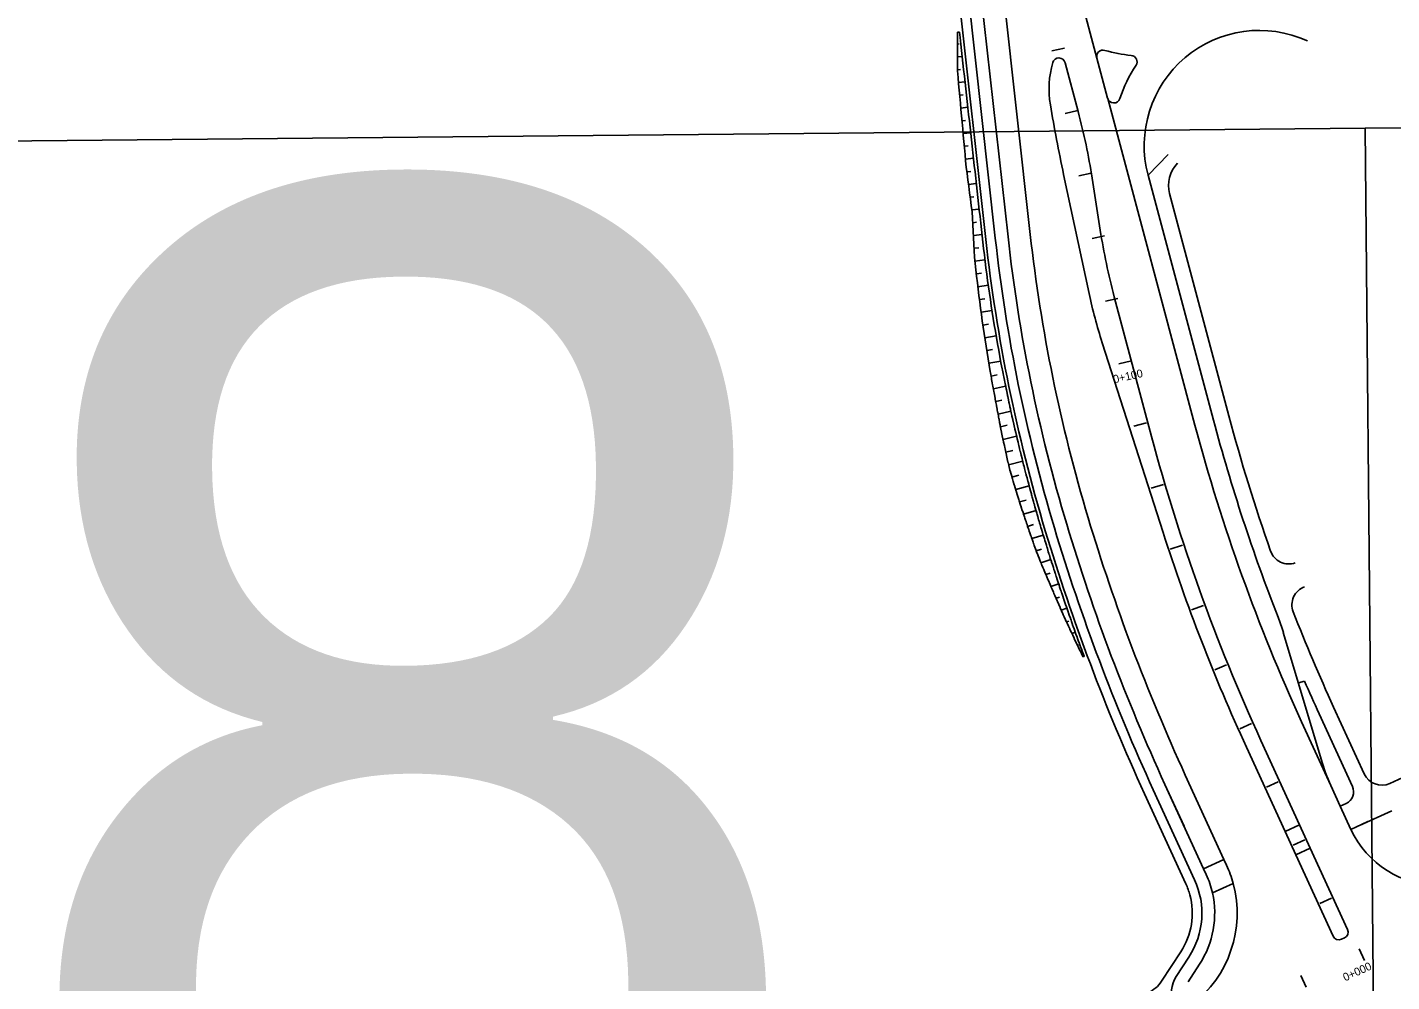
# Model space of a CAD drawing. Extents: x 6503541 to 6503743, y 5888004 to 5888145.
# Drawn here: x 6503621.98 to 6503627.1, y 5888065.98 to 5888069.56 of the extents above; entities that cross this region are included whole.
import ezdxf

# ---------------------------------------------------------------- set-up
doc = ezdxf.new("R2010")
doc.units = 0
doc.layers.add('12', color=7, linetype='Continuous')
doc.layers.add('tabela', color=7, linetype='Continuous')

msp = doc.modelspace()

# ---------------------------------------------------------------- linework, layer by layer
at = {"layer": '12'}
for p, q in [((6503625.4273, 5888070.0972), (6503625.5753, 5888068.7684)), ((6503625.4631, 5888070.1011), (6503625.6111, 5888068.7724)), ((6503625.5108, 5888070.1065), (6503625.6588, 5888068.7777)), ((6503625.5943, 5888070.1158), (6503625.7422, 5888068.787)), ((6503625.9923, 5888069.4479), (6503625.8125, 5888070.1213)), ((6503625.9216, 5888069.2472), (6503625.8727, 5888069.4307)), ((6503626.0324, 5888069.2976), (6503625.9923, 5888069.4479)), ((6503626.3595, 5888068.0721), (6503626.0325, 5888069.297)), ((6503625.8673, 5888069.012), (6503625.9627, 5888068.5658)), ((6503625.9742, 5888068.9979), (6503626.0046, 5888068.8027)), ((6503626.429, 5888068.0907), (6503626.1841, 5888069.0085)), ((6503626.487, 5888068.1062), (6503626.2645, 5888068.9399)), ((6503626.1972, 5888068.0288), (6503626.0571, 5888068.5534)), ((6503626.012, 5888068.3807), (6503626.2401, 5888067.6695)), ((6503626.487, 5888068.1062), (6503626.4909, 5888068.0915)), ((6503626.6911, 5888067.2944), (6503626.8337, 5888066.8153)), ((6503626.7474, 5888067.1053), (6503626.7704, 5888067.1121)), ((6503626.9948, 5888066.7636), (6503626.8797, 5888067.0145)), ((6503626.8693, 5888066.7205), (6503626.7598, 5888066.9595)), ((6503626.9503, 5888066.7168), (6503626.8252, 5888066.9895)), ((6503626.6976, 5888066.5481), (6503626.5525, 5888066.8645)), ((6503626.7521, 5888066.5731), (6503626.607, 5888066.8895)), ((6503626.4685, 5888066.4431), (6503626.3234, 5888066.7595)), ((6503627.0903, 5888066.7282), (6503627.156, 5888066.7583)), ((6503626.3585, 5888066.3663), (6503626.2034, 5888066.7044)), ((6503626.3192, 5888066.5672), (6503626.2471, 5888066.7244)), ((6503626.3921, 5888066.4081), (6503626.2471, 5888066.7244)), ((6503626.9048, 5888066.6431), (6503626.8693, 5888066.7205)), ((6503626.3258, 5888066.3512), (6503626.1707, 5888066.6894)), ((6503626.9266, 5888066.6531), (6503626.9048, 5888066.6431)), ((6503626.9448, 5888066.5559), (6503626.9048, 5888066.6431)), ((6503627.0975, 5888066.6259), (6503626.9767, 5888066.5705)), ((6503626.6976, 5888066.5481), (6503626.7521, 5888066.5731)), ((6503626.7376, 5888066.4608), (6503626.6976, 5888066.5481)), ((6503626.7921, 5888066.4858), (6503626.7521, 5888066.5731)), ((6503627.0079, 5888066.5848), (6503626.9448, 5888066.5559)), ((6503626.3921, 5888066.4081), (6503626.4685, 5888066.4431)), ((6503626.4785, 5888066.4213), (6503626.4685, 5888066.4431)), ((6503626.7376, 5888066.4608), (6503626.7921, 5888066.4858)), ((6503626.8776, 5888066.1554), (6503626.7376, 5888066.4608)), ((6503626.9321, 5888066.1804), (6503626.7921, 5888066.4858)), ((6503626.4021, 5888066.3863), (6503626.3921, 5888066.4081)), ((6503626.4253, 5888066.3177), (6503626.503, 5888066.3533)), ((6503626.9203, 5888066.1486), (6503626.9094, 5888066.1436)), ((6503626.3068, 5888066.0968), (6503626.2348, 5888065.9866)), ((6503626.3369, 5888066.0771), (6503626.2896, 5888066.0046)), ((6503626.3771, 5888066.0508), (6503626.3338, 5888065.9845))]:
    msp.add_line(p, q, dxfattribs=at)
for points in [[(6503625.4688, 5888069.5449), (6503625.4766, 5888069.5458)], [(6503625.9396, 5888067.2029), (6503625.9391, 5888067.2039), (6503625.9337, 5888067.2152), (6503625.9291, 5888067.2248), (6503625.9283, 5888067.2266), (6503625.9228, 5888067.238), (6503625.9181, 5888067.248), (6503625.9175, 5888067.2494), (6503625.9121, 5888067.2608), (6503625.9072, 5888067.2712), (6503625.9067, 5888067.2722), (6503625.9014, 5888067.2836), (6503625.8963, 5888067.2945), (6503625.896, 5888067.2951), (6503625.8907, 5888067.3065), (6503625.8901, 5888067.3079), (6503625.8855, 5888067.3178), (6503625.8854, 5888067.318), (6503625.8802, 5888067.3294), (6503625.878, 5888067.3342), (6503625.8749, 5888067.3409), (6503625.8748, 5888067.3412), (6503625.8697, 5888067.3524), (6503625.8661, 5888067.3605), (6503625.8645, 5888067.3639), (6503625.8642, 5888067.3646), (6503625.8594, 5888067.3754), (6503625.8542, 5888067.3869), (6503625.8542, 5888067.387), (6503625.8537, 5888067.3881), (6503625.8491, 5888067.3985), (6503625.844, 5888067.4101), (6503625.8433, 5888067.4116), (6503625.8425, 5888067.4134), (6503625.8389, 5888067.4216), (6503625.8339, 5888067.4332), (6503625.833, 5888067.4352), (6503625.831, 5888067.4399), (6503625.8288, 5888067.4448), (6503625.8238, 5888067.4564), (6503625.8228, 5888067.4588), (6503625.8195, 5888067.4665), (6503625.8189, 5888067.468), (6503625.8139, 5888067.4797), (6503625.8127, 5888067.4825), (6503625.809, 5888067.4913), (6503625.8082, 5888067.4932), (6503625.8041, 5888067.5029), (6503625.8027, 5888067.5062), (6503625.7992, 5888067.5146), (6503625.797, 5888067.5199), (6503625.7943, 5888067.5263), (6503625.7928, 5888067.53), (6503625.7895, 5888067.5379), (6503625.7859, 5888067.5466), (6503625.7847, 5888067.5496), (6503625.783, 5888067.5538), (6503625.7799, 5888067.5613), (6503625.7751, 5888067.5731), (6503625.775, 5888067.5735), (6503625.7733, 5888067.5776), (6503625.7704, 5888067.5848), (6503625.7658, 5888067.5966), (6503625.7644, 5888067.6004), (6503625.764, 5888067.6016), (6503625.7615, 5888067.6084), (6503625.7573, 5888067.6203), (6503625.7553, 5888067.6258), (6503625.7547, 5888067.6277), (6503625.753, 5888067.6322), (6503625.7488, 5888067.6441), (6503625.7468, 5888067.6501), (6503625.7451, 5888067.655), (6503625.7447, 5888067.656), (6503625.7405, 5888067.668), (6503625.7383, 5888067.6744), (6503625.7364, 5888067.6799), (6503625.7356, 5888067.6823), (6503625.7323, 5888067.6919), (6503625.73, 5888067.6987), (6503625.7283, 5888067.7038), (6503625.7263, 5888067.7097), (6503625.7243, 5888067.7158), (6503625.7218, 5888067.7231), (6503625.7203, 5888067.7278), (6503625.7172, 5888067.7372), (6503625.7163, 5888067.7398), (6503625.7138, 5888067.7475), (6503625.7124, 5888067.7518), (6503625.7085, 5888067.7638), (6503625.7082, 5888067.7647), (6503625.7059, 5888067.772), (6503625.7046, 5888067.7758), (6503625.7008, 5888067.7878), (6503625.6994, 5888067.7922), (6503625.6981, 5888067.7965), (6503625.697, 5888067.7999), (6503625.6932, 5888067.8119), (6503625.6908, 5888067.8198), (6503625.6904, 5888067.8211), (6503625.6895, 5888067.824), (6503625.6858, 5888067.8361), (6503625.6828, 5888067.8457), (6503625.6823, 5888067.8475), (6503625.6821, 5888067.8481), (6503625.6784, 5888067.8602), (6503625.6754, 5888067.8703), (6503625.6748, 5888067.8723), (6503625.674, 5888067.8752), (6503625.6712, 5888067.8844), (6503625.6681, 5888067.895), (6503625.6677, 5888067.8966), (6503625.6658, 5888067.903), (6503625.6642, 5888067.9087), (6503625.6616, 5888067.9198), (6503625.6614, 5888067.921), (6503625.6591, 5888067.9311), (6503625.6586, 5888067.9333), (6503625.6559, 5888067.9449), (6503625.6558, 5888067.9457), (6503625.653, 5888067.958), (6503625.6527, 5888067.9594), (6503625.6504, 5888067.9701), (6503625.6503, 5888067.9703), (6503625.6477, 5888067.9827), (6503625.6466, 5888067.9877), (6503625.645, 5888067.995), (6503625.645, 5888067.9952), (6503625.6424, 5888068.0074), (6503625.6406, 5888068.016), (6503625.6398, 5888068.0198), (6503625.6397, 5888068.0204), (6503625.6373, 5888068.0321), (6503625.6348, 5888068.0443), (6503625.6347, 5888068.0445), (6503625.6345, 5888068.0456), (6503625.6322, 5888068.0569), (6503625.6298, 5888068.0693), (6503625.6295, 5888068.0708), (6503625.6291, 5888068.0727), (6503625.6274, 5888068.0817), (6503625.625, 5888068.0941), (6503625.6246, 5888068.0961), (6503625.6236, 5888068.1011), (6503625.6226, 5888068.1065), (6503625.6203, 5888068.1189), (6503625.6198, 5888068.1213), (6503625.6183, 5888068.1295), (6503625.6179, 5888068.1313), (6503625.6157, 5888068.1437), (6503625.6151, 5888068.1466), (6503625.6134, 5888068.1561), (6503625.6111, 5888068.1685), (6503625.6104, 5888068.1719), (6503625.6087, 5888068.1809), (6503625.6064, 5888068.1933), (6503625.6057, 5888068.1972), (6503625.6041, 5888068.2058), (6503625.6019, 5888068.2182), (6503625.6011, 5888068.2224), (6503625.5996, 5888068.2306), (6503625.5974, 5888068.243), (6503625.5966, 5888068.2477), (6503625.5952, 5888068.2554), (6503625.5931, 5888068.2679), (6503625.5923, 5888068.2727), (6503625.5882, 5888068.2964), (6503625.5843, 5888068.3201), (6503625.5804, 5888068.3438), (6503625.5766, 5888068.3676), (6503625.573, 5888068.3913), (6503625.5694, 5888068.4151), (6503625.5658, 5888068.4389), (6503625.5624, 5888068.4627), (6503625.5591, 5888068.4865), (6503625.5558, 5888068.5104), (6503625.5527, 5888068.5342), (6503625.5496, 5888068.5581), (6503625.5467, 5888068.582), (6503625.5438, 5888068.6059), (6503625.541, 5888068.6299), (6503625.5383, 5888068.6539), (6503625.5356, 5888068.6778), (6503625.5334, 5888068.7019), (6503625.5319, 5888068.7261), (6503625.5306, 5888068.7504), (6503625.5293, 5888068.7746), (6503625.528, 5888068.7989), (6503625.5267, 5888068.8232), (6503625.5254, 5888068.8474), (6503625.5237, 5888068.8716), (6503625.5207, 5888068.8955), (6503625.5176, 5888068.9194), (6503625.5146, 5888068.9433), (6503625.5115, 5888068.9672), (6503625.5085, 5888068.9911), (6503625.5055, 5888069.015), (6503625.5024, 5888069.0389), (6503625.4997, 5888069.0628), (6503625.4975, 5888069.0869), (6503625.4953, 5888069.111), (6503625.4932, 5888069.1351), (6503625.491, 5888069.1591), (6503625.4888, 5888069.1832), (6503625.4866, 5888069.2073), (6503625.4844, 5888069.2314), (6503625.4823, 5888069.2554), (6503625.4801, 5888069.2795), (6503625.4779, 5888069.3036), (6503625.4757, 5888069.3277), (6503625.4735, 5888069.3517), (6503625.4714, 5888069.3758), (6503625.4693, 5888069.3999), (6503625.4694, 5888069.4245), (6503625.4695, 5888069.4491), (6503625.4696, 5888069.4736), (6503625.4697, 5888069.4982), (6503625.4699, 5888069.5228), (6503625.4688, 5888069.5449)], [(6503625.9441, 5888067.2045), (6503625.9437, 5888067.2056), (6503625.9394, 5888067.2173), (6503625.9357, 5888067.2272), (6503625.935, 5888067.2291), (6503625.9307, 5888067.2409), (6503625.9269, 5888067.2512), (6503625.9264, 5888067.2526), (6503625.9221, 5888067.2644), (6503625.9182, 5888067.2752), (6503625.9178, 5888067.2762), (6503625.9136, 5888067.288), (6503625.9096, 5888067.2992), (6503625.9093, 5888067.2998), (6503625.9051, 5888067.3116), (6503625.9046, 5888067.3131), (6503625.901, 5888067.3233), (6503625.9009, 5888067.3235), (6503625.8968, 5888067.3353), (6503625.8951, 5888067.3402), (6503625.8926, 5888067.3471), (6503625.8925, 5888067.3474), (6503625.8885, 5888067.359), (6503625.8856, 5888067.3673), (6503625.8844, 5888067.3708), (6503625.8841, 5888067.3715), (6503625.8803, 5888067.3827), (6503625.8762, 5888067.3945), (6503625.8762, 5888067.3945), (6503625.8758, 5888067.3957), (6503625.8722, 5888067.4064), (6503625.8681, 5888067.4183), (6503625.8676, 5888067.4198), (6503625.867, 5888067.4217), (6503625.8641, 5888067.4301), (6503625.8601, 5888067.442), (6503625.8594, 5888067.444), (6503625.8578, 5888067.4489), (6503625.8561, 5888067.4539), (6503625.8522, 5888067.4658), (6503625.8514, 5888067.4683), (6503625.8488, 5888067.4762), (6503625.8482, 5888067.4777), (6503625.8443, 5888067.4896), (6503625.8434, 5888067.4925), (6503625.8404, 5888067.5015), (6503625.8398, 5888067.5035), (6503625.8365, 5888067.5135), (6503625.8355, 5888067.5168), (6503625.8327, 5888067.5254), (6503625.8309, 5888067.5308), (6503625.8288, 5888067.5373), (6503625.8276, 5888067.5411), (6503625.825, 5888067.5493), (6503625.8222, 5888067.5582), (6503625.8212, 5888067.5612), (6503625.8199, 5888067.5655), (6503625.8174, 5888067.5732), (6503625.8137, 5888067.5852), (6503625.8135, 5888067.5856), (6503625.8122, 5888067.5898), (6503625.8099, 5888067.5971), (6503625.8062, 5888067.6091), (6503625.805, 5888067.613), (6503625.8046, 5888067.6142), (6503625.8025, 5888067.6211), (6503625.7988, 5888067.6331), (6503625.7971, 5888067.6386), (6503625.7966, 5888067.6405), (6503625.7952, 5888067.6451), (6503625.7915, 5888067.6571), (6503625.7897, 5888067.6631), (6503625.7882, 5888067.668), (6503625.7879, 5888067.6691), (6503625.7843, 5888067.6811), (6503625.7824, 5888067.6875), (6503625.7807, 5888067.6931), (6503625.78, 5888067.6955), (6503625.7772, 5888067.7051), (6503625.7751, 5888067.712), (6503625.7736, 5888067.7171), (6503625.7719, 5888067.7231), (6503625.7701, 5888067.7292), (6503625.768, 5888067.7365), (6503625.7666, 5888067.7412), (6503625.7639, 5888067.7507), (6503625.7632, 5888067.7533), (6503625.761, 5888067.7611), (6503625.7597, 5888067.7653), (6503625.7563, 5888067.7774), (6503625.7561, 5888067.7783), (6503625.754, 5888067.7857), (6503625.753, 5888067.7895), (6503625.7496, 5888067.8016), (6503625.7484, 5888067.806), (6503625.7472, 5888067.8103), (6503625.7463, 5888067.8137), (6503625.743, 5888067.8258), (6503625.7408, 5888067.8337), (6503625.7405, 5888067.8349), (6503625.7397, 5888067.8379), (6503625.7364, 5888067.85), (6503625.7338, 5888067.8596), (6503625.7333, 5888067.8614), (6503625.7332, 5888067.8621), (6503625.73, 5888067.8742), (6503625.7273, 5888067.8843), (6503625.7268, 5888067.8863), (6503625.726, 5888067.8892), (6503625.7236, 5888067.8985), (6503625.7209, 5888067.909), (6503625.7205, 5888067.9106), (6503625.7188, 5888067.917), (6503625.7174, 5888067.9227), (6503625.7146, 5888067.9337), (6503625.7143, 5888067.9349), (6503625.7118, 5888067.9449), (6503625.7112, 5888067.9471), (6503625.7083, 5888067.9585), (6503625.7082, 5888067.9592), (6503625.7051, 5888067.9714), (6503625.7048, 5888067.9727), (6503625.7022, 5888067.9833), (6503625.7022, 5888067.9836), (6503625.6992, 5888067.9957), (6503625.698, 5888068.0006), (6503625.6963, 5888068.0079), (6503625.6962, 5888068.0081), (6503625.6933, 5888068.0201), (6503625.6913, 5888068.0286), (6503625.6904, 5888068.0323), (6503625.6903, 5888068.033), (6503625.6876, 5888068.0445), (6503625.6848, 5888068.0566), (6503625.6847, 5888068.0567), (6503625.6845, 5888068.0578), (6503625.6819, 5888068.069), (6503625.6791, 5888068.0812), (6503625.6788, 5888068.0827), (6503625.6784, 5888068.0846), (6503625.6764, 5888068.0934), (6503625.6736, 5888068.1056), (6503625.6732, 5888068.1076), (6503625.6721, 5888068.1126), (6503625.6709, 5888068.1179), (6503625.6682, 5888068.1301), (6503625.6677, 5888068.1325), (6503625.6659, 5888068.1406), (6503625.6655, 5888068.1424), (6503625.6629, 5888068.1546), (6503625.6623, 5888068.1575), (6503625.6603, 5888068.1669), (6503625.6577, 5888068.1791), (6503625.657, 5888068.1825), (6503625.6551, 5888068.1914), (6503625.6526, 5888068.2037), (6503625.6518, 5888068.2075), (6503625.6501, 5888068.216), (6503625.6476, 5888068.2282), (6503625.6467, 5888068.2325), (6503625.6451, 5888068.2405), (6503625.6427, 5888068.2528), (6503625.6417, 5888068.2575), (6503625.6402, 5888068.2651), (6503625.6379, 5888068.2774), (6503625.6369, 5888068.2823), (6503625.6324, 5888068.3059), (6503625.628, 5888068.3295), (6503625.6237, 5888068.3531), (6503625.6195, 5888068.3767), (6503625.6154, 5888068.4004), (6503625.6113, 5888068.4241), (6503625.6074, 5888068.4477), (6503625.6035, 5888068.4715), (6503625.5998, 5888068.4952), (6503625.5961, 5888068.519), (6503625.5925, 5888068.5427), (6503625.589, 5888068.5665), (6503625.5856, 5888068.5904), (6503625.5823, 5888068.6142), (6503625.5791, 5888068.638), (6503625.576, 5888068.6619), (6503625.5729, 5888068.6858), (6503625.57, 5888068.7097), (6503625.5672, 5888068.7337), (6503625.5644, 5888068.7576), (6503625.5617, 5888068.7816), (6503625.5591, 5888068.8056), (6503625.5564, 5888068.8295), (6503625.5537, 5888068.8535), (6503625.5511, 5888068.8775), (6503625.5484, 5888068.9014), (6503625.5457, 5888068.9254), (6503625.543, 5888068.9494), (6503625.5404, 5888068.9734), (6503625.5377, 5888068.9973), (6503625.535, 5888069.0213), (6503625.5324, 5888069.0453), (6503625.5297, 5888069.0692), (6503625.527, 5888069.0932), (6503625.5244, 5888069.1172), (6503625.5217, 5888069.1412), (6503625.519, 5888069.1651), (6503625.5164, 5888069.1891), (6503625.5137, 5888069.2131), (6503625.511, 5888069.237), (6503625.5083, 5888069.261), (6503625.5057, 5888069.285), (6503625.503, 5888069.309), (6503625.5003, 5888069.3329), (6503625.4977, 5888069.3569), (6503625.495, 5888069.3809), (6503625.4923, 5888069.4048), (6503625.4897, 5888069.4288), (6503625.487, 5888069.4528), (6503625.4843, 5888069.4768), (6503625.4816, 5888069.5007), (6503625.479, 5888069.5247), (6503625.4766, 5888069.5458)], [(6503625.4698, 5888069.5008), (6503625.4756, 5888069.5014)], [(6503625.8704, 5888069.4856), (6503625.8234, 5888069.4756)], [(6503625.4695, 5888069.4525), (6503625.4868, 5888069.4544)], [(6503625.4693, 5888069.4041), (6503625.4807, 5888069.4054)], [(6503625.4731, 5888069.3563), (6503625.4974, 5888069.359)], [(6503625.4775, 5888069.3085), (6503625.4901, 5888069.3099)], [(6503625.4818, 5888069.2606), (6503625.5081, 5888069.2636)], [(6503625.4861, 5888069.2128), (6503625.4997, 5888069.2143)], [(6503625.9205, 5888069.251), (6503625.8736, 5888069.2409)], [(6503625.4904, 5888069.165), (6503625.5187, 5888069.1682)], [(6503625.4948, 5888069.1172), (6503625.5094, 5888069.1188)], [(6503625.4991, 5888069.0694), (6503625.5293, 5888069.0727)], [(6503626.1841, 5888069.0085), (6503626.259, 5888069.0869)], [(6503625.5046, 5888069.0217), (6503625.5196, 5888069.0234)], [(6503625.9707, 5888069.0163), (6503625.9237, 5888069.0062)], [(6503625.5107, 5888068.9741), (6503625.5399, 5888068.9773)], [(6503625.5167, 5888068.9265), (6503625.531, 5888068.928)], [(6503625.5228, 5888068.8788), (6503625.5506, 5888068.8819)], [(6503625.5263, 5888068.8309), (6503625.5411, 5888068.8326)], [(6503625.5288, 5888068.7829), (6503625.5612, 5888068.7865)], [(6503626.0209, 5888068.7816), (6503625.9739, 5888068.7715)], [(6503625.5314, 5888068.7347), (6503625.549, 5888068.7368)], [(6503625.5348, 5888068.6865), (6503625.5723, 5888068.6912)], [(6503625.54, 5888068.6385), (6503625.5592, 5888068.641)], [(6503625.5456, 5888068.5905), (6503625.5848, 5888068.596)], [(6503625.5516, 5888068.5426), (6503625.5716, 5888068.5455)], [(6503626.071, 5888068.5469), (6503626.0241, 5888068.5368)], [(6503625.558, 5888068.4947), (6503625.5989, 5888068.501)], [(6503625.5647, 5888068.4468), (6503625.5856, 5888068.4502)], [(6503625.5718, 5888068.399), (6503625.6144, 5888068.4063)], [(6503625.5792, 5888068.3512), (6503625.601, 5888068.3551)], [(6503625.5871, 5888068.3035), (6503625.6313, 5888068.3118)], [(6503626.0746, 5888068.302), (6503626.1214, 5888068.3124)], [(6503625.5952, 5888068.2558), (6503625.6178, 5888068.2602)], [(6503625.6037, 5888068.2082), (6503625.6497, 5888068.2176)], [(6503625.6126, 5888068.1606), (6503625.636, 5888068.1656)], [(6503625.6214, 5888068.113), (6503625.6696, 5888068.1237)], [(6503626.1775, 5888068.0799), (6503626.131, 5888068.0679)], [(6503625.6305, 5888068.0655), (6503625.6553, 5888068.0712)], [(6503625.6402, 5888068.0181), (6503625.691, 5888068.0301)], [(6503625.6503, 5888067.9707), (6503625.6762, 5888067.977)], [(6503625.6608, 5888067.9234), (6503625.7138, 5888067.9368)], [(6503625.6735, 5888067.8767), (6503625.6996, 5888067.8835)], [(6503625.6875, 5888067.8303), (6503625.738, 5888067.8439)], [(6503626.2413, 5888067.8494), (6503626.1952, 5888067.8358)], [(6503625.702, 5888067.7841), (6503625.7263, 5888067.7909)], [(6503625.7169, 5888067.738), (6503625.7637, 5888067.7514)], [(6503625.7323, 5888067.6921), (6503625.7547, 5888067.6987)], [(6503625.7481, 5888067.6464), (6503625.7908, 5888067.6593)], [(6503626.3127, 5888067.6211), (6503626.2671, 5888067.606)], [(6503625.7642, 5888067.6009), (6503625.7846, 5888067.6071)], [(6503625.7821, 5888067.5559), (6503625.8192, 5888067.5676)], [(6503625.8006, 5888067.5112), (6503625.8172, 5888067.5165)], [(6503625.8195, 5888067.4666), (6503625.8487, 5888067.4763)], [(6503625.8387, 5888067.4222), (6503625.8513, 5888067.4265)], [(6503625.8582, 5888067.378), (6503625.8794, 5888067.3853)], [(6503626.3917, 5888067.3953), (6503626.3467, 5888067.3787)], [(6503625.8781, 5888067.334), (6503625.8866, 5888067.337)], [(6503625.8983, 5888067.2901), (6503625.9112, 5888067.2947)], [(6503625.9189, 5888067.2464), (6503625.9232, 5888067.248)], [(6503625.9396, 5888067.2029), (6503625.9441, 5888067.2045)], [(6503626.4782, 5888067.1723), (6503626.4337, 5888067.1542)], [(6503626.572, 5888066.9523), (6503626.5282, 5888066.9328)], [(6503626.6716, 5888066.7342), (6503626.628, 5888066.7142)], [(6503626.7717, 5888066.5161), (6503626.728, 5888066.4961)], [(6503626.8717, 5888066.2979), (6503626.828, 5888066.2779)], [(6503626.9951, 5888066.0641), (6503626.9751, 5888066.1077)], [(6503626.777, 5888065.9641), (6503626.7569, 5888066.0077)]]:
    msp.add_lwpolyline(points, dxfattribs=at)
for centre, radius, start, end in [((6503626.6014, 5888069.1199), 0.432, 65.3921, 194.9442), ((6503626.0154, 5888069.4541), 0.024, 73.8073, 194.9442), ((6503626.1761, 5888070.0072), 0.552, 253.8073, 264.2802), ((6503626.1727, 5888069.3326), 0.36, 164.1342, 189.4728), ((6503625.8495, 5888069.4245), 0.024, 14.9442, 164.1342), ((6503626.6014, 5888069.1199), 0.552, 146.9446, 161.3869), ((6503626.1187, 5888069.4341), 0.024, 326.9446, 84.2802), ((6503631.6174, 5888070.2411), 5.88, 189.47282, 192.06562), ((6503626.0556, 5888069.3038), 0.024, 194.9442, 341.3869), ((6503623.6028, 5888068.6283), 2.4, 8.8577, 14.9442), ((6503626.3804, 5888068.9708), 0.12, 136.2843, 194.9395), ((6503628.376, 5888069.1723), 2.4, 188.8577, 194.9442), ((6503631.7054, 5888069.4511), 6.168, 186.35503, 196.72995), ((6503631.7054, 5888069.4511), 6.132, 186.35503, 196.72995), ((6503631.7054, 5888069.4511), 6.084, 186.35503, 196.72995), ((6503631.7054, 5888069.4511), 6, 186.35503, 196.72995), ((6503627.8403, 5888068.9672), 1.92, 192.0656, 197.7841), ((6503633.1246, 5888069.8778), 6.93, 194.94399, 201.37913), ((6503633.1246, 5888069.8778), 6.87, 194.94399, 199.3721), ((6503633.1246, 5888069.8778), 7.17, 194.94437, 204.63106), ((6503633.1246, 5888069.8778), 7.002, 194.94399, 204.63106), ((6503633.1246, 5888069.8778), 7.482, 196.72995, 204.63106), ((6503633.1246, 5888069.8778), 7.65, 196.73018, 204.63106), ((6503633.1246, 5888069.8778), 7.614, 196.73018, 204.63106), ((6503633.1246, 5888069.8778), 7.566, 196.73018, 204.63106), ((6503633.1246, 5888069.8778), 7.23, 197.7839, 204.63094), ((6503626.7115, 5888067.6229), 0.072, 199.3721, 289.9789), ((6503626.7951, 5888067.3979), 0.072, 109.9789, 201.395), ((6503633.1246, 5888069.8778), 6.87, 201.39505, 204.63106), ((6503626.0011, 5888067.089), 0.72, 16.5705, 21.3791), ((6503633.1246, 5888069.8778), 6.93, 203.52087, 204.63106), ((6503627.5238, 5888067.0206), 0.72, 196.5705, 204.6311), ((6503627.0602, 5888066.7936), 0.072, 204.6311, 294.6311), ((6503626.9066, 5888066.6968), 0.048, 294.6311, 24.6311), ((6503627.2721, 5888066.7059), 0.36, 204.6311, 271.0529), ((6503626.0858, 5888066.2412), 0.432, 15.037, 24.6311), ((6503626.0858, 5888066.2412), 0.264, 15.037, 24.6307), ((6503626.0858, 5888066.2412), 0.3, 326.8345, 24.6317), ((6503626.0858, 5888066.2412), 0.432, 307.4706, 15.037), ((6503626.0858, 5888066.2412), 0.348, 12.6905, 24.6307), ((6503626.0858, 5888066.2412), 0.264, 326.8345, 15.037), ((6503626.0858, 5888066.2412), 0.348, 326.8345, 12.6905), ((6503626.8994, 5888066.1654), 0.024, 204.6311, 294.6311), ((6503626.9103, 5888066.1704), 0.024, 294.6311, 24.6311), ((6503626.1343, 5888066.0522), 0.12, 294.6311, 326.8353), ((6503626.38, 5888065.9455), 0.108, 146.8353, 204.6311)]:
    msp.add_arc(centre, radius, start, end, dxfattribs=at)
at = {"layer": 'tabela'}
for p, q in [((6503626.998, 5888069.1851), (6503634.2334, 5888069.2527)), ((6503619.7626, 5888069.1175), (6503626.998, 5888069.1851)), ((6503627.0449, 5888064.165), (6503626.998, 5888069.1851)), ((6503626.998, 5888069.1851), (6503627.0449, 5888064.165))]:
    msp.add_line(p, q, dxfattribs=at)

# ---------------------------------------------------------------- texts
at = {"layer": '12'}
for s, height, rotation, p in [('8', 4.223, 0.7393, (6503621.8715, 5888064.7245)), ('0+100', 0.03, 12.5993, (6503626.0567, 5888068.2284)), ('0+000', 0.03, 24.6311, (6503626.9231, 5888065.9853))]:
    msp.add_text(s, height=height, rotation=rotation, dxfattribs=at).set_placement(p)

doc.saveas('drawing.dxf')
